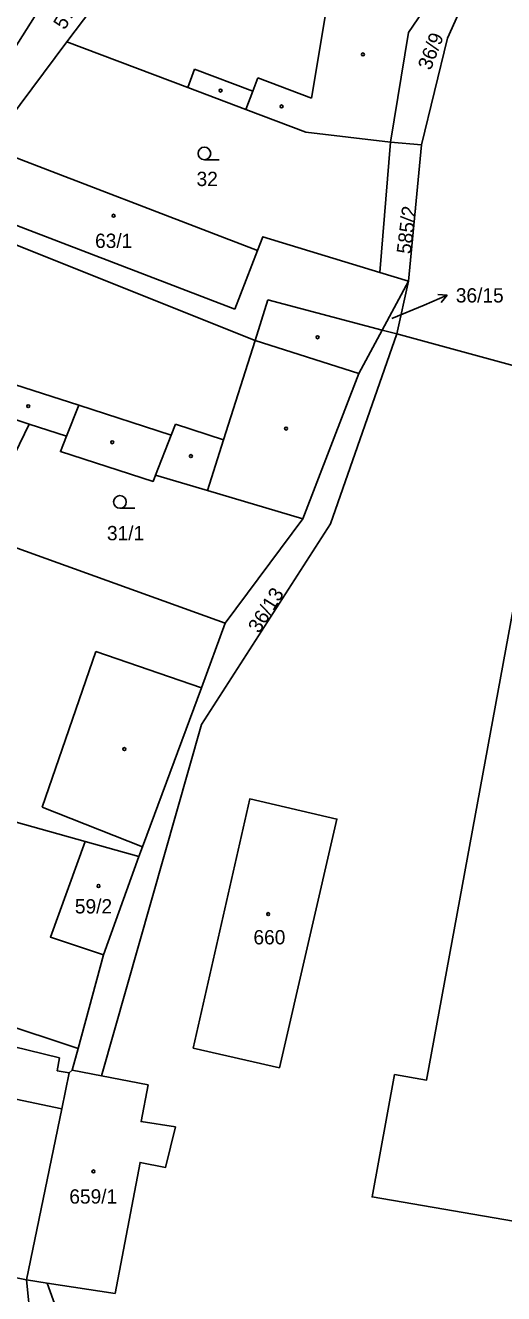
# Model space of a CAD drawing. Extents: x -783948 to -781889, y -1005870 to -1004430.
# Drawn here: x -782580.6 to -782523.7, y -1005661.9 to -1005511.3 of the extents above; entities that cross this region are included whole.
import ezdxf

# ---------------------------------------------------------------- set-up
doc = ezdxf.new("R2010")
doc.units = 0
for name, color, linetype in [('Vrstva 1', 7, 'Continuous'), ('Vrstva 2', 7, 'Continuous'), ('Vrstva 3', 7, 'Continuous'), ('Vrstva 4', 7, 'Continuous'), ('Vrstva 5', 7, 'Continuous'), ('Vrstva 7', 7, 'Continuous')]:
    doc.layers.add(name, color=color, linetype=linetype)

msp = doc.modelspace()

# ---------------------------------------------------------------- linework, layer by layer
at = {"layer": 'Vrstva 1'}
for p, q in [((-782575.65, -1005513.29), (-782585.01, -1005525.81)), ((-782538.44, -1005540.69), (-782537.19, -1005525.21)), ((-782537.19, -1005525.21), (-782533.51, -1005525.52)), ((-782533.51, -1005525.52), (-782535.06, -1005541.72)), ((-782535.06, -1005541.72), (-782538.44, -1005540.69)), ((-782538.17, -1005547.51), (-782535.06, -1005541.72)), ((-782536.45, -1005547.96), (-782535.06, -1005541.72)), ((-782540.95, -1005552.68), (-782538.17, -1005547.51)), ((-782536.45, -1005547.96), (-782538.17, -1005547.51)), ((-782547.61, -1005569.93), (-782540.95, -1005552.68)), ((-782556.83, -1005582.33), (-782547.61, -1005569.93)), ((-782556.83, -1005582.33), (-782585.34, -1005572.07)), ((-782573.46, -1005608.26), (-782584.31, -1005605.25)), ((-782567.1, -1005610.03), (-782573.46, -1005608.26)), ((-782571.28, -1005621.73), (-782567.1, -1005610.03)), ((-782574.31, -1005632.82), (-782571.28, -1005621.73)), ((-782574.31, -1005632.82), (-782587.97, -1005628.34)), ((-782575.02, -1005635.4), (-782574.31, -1005632.82)), ((-782571.53, -1005636.08), (-782575.02, -1005635.4)), ((-782565.98, -1005637.15), (-782571.53, -1005636.08)), ((-782589.64, -1005637.21), (-782576.26, -1005640.02)), ((-782580.46, -1005660.33), (-782576.26, -1005640.02)), ((-782593.5, -1005657.59), (-782580.46, -1005660.33)), ((-782580.46, -1005660.33), (-782577.99, -1005660.71)), ((-782580.46, -1005660.33), (-782579.32, -1005670.89)), ((-782577.99, -1005660.71), (-782569.93, -1005661.94))]:
    msp.add_line(p, q, dxfattribs=at)
for points in [[(-782548.22, -1005452.35), (-782556.43, -1005467.86), (-782566.82, -1005490.19), (-782588.5, -1005524.48)], [(-782562.27, -1005486.8), (-782562.84, -1005488.54), (-782571.69, -1005508), (-782575.65, -1005513.29)], [(-782533.51, -1005525.52), (-782530.41, -1005512.83), (-782526.67, -1005504.45)], [(-782537.19, -1005525.21), (-782535.04, -1005512.19), (-782532.24, -1005508.02)], [(-782575.65, -1005513.29), (-782561.29, -1005518.71), (-782554.37, -1005521.32), (-782547.24, -1005524), (-782537.19, -1005525.21)], [(-782538.44, -1005540.69), (-782552.38, -1005536.44), (-782553, -1005538.05), (-782585.01, -1005525.81)], [(-782591.08, -1005533.66), (-782553.28, -1005548.74), (-782540.95, -1005552.68)], [(-782536.45, -1005547.96), (-782544.31, -1005570.51), (-782559.66, -1005594.35), (-782571.53, -1005636.08)], [(-782452.94, -1005571.06), (-782456.68, -1005569.69), (-782536.45, -1005547.96)], [(-782580.15, -1005558.68), (-782584, -1005557.44), (-782585.78, -1005556.87), (-782591.85, -1005554.92), (-782599.07, -1005552.6)], [(-782585.34, -1005572.07), (-782582.34, -1005564.85), (-782583, -1005564.57), (-782580.15, -1005558.68)], [(-782580.15, -1005558.68), (-782575.69, -1005560.12), (-782576.41, -1005561.94), (-782565.41, -1005565.48), (-782565.11, -1005564.73), (-782558.94, -1005566.58), (-782547.61, -1005569.93)], [(-782517.64, -1005572.78), (-782521.05, -1005572.25), (-782532.9, -1005636.58), (-782536.7, -1005635.93), (-782539.38, -1005650.47), (-782518.91, -1005653.99), (-782516.23, -1005639.45), (-782520.22, -1005638.76), (-782509.61, -1005574.13), (-782510.94, -1005573.92)], [(-782567.1, -1005610.03), (-782566.67, -1005608.87), (-782559.67, -1005589.99), (-782556.83, -1005582.33)], [(-782550.4, -1005635.12), (-782560.63, -1005632.78), (-782553.91, -1005603.2), (-782543.56, -1005605.59), (-782550.4, -1005635.12)], [(-782571.28, -1005621.73), (-782577.6, -1005619.6), (-782573.46, -1005608.26)], [(-782576.26, -1005640.02), (-782575.37, -1005635.74), (-782575.02, -1005635.4)], [(-782569.93, -1005661.94), (-782566.95, -1005646.36), (-782563.92, -1005646.96), (-782562.75, -1005642.15), (-782566.84, -1005641.52), (-782565.98, -1005637.15)], [(-782577.99, -1005660.71), (-782575.15, -1005668.63), (-782553.77, -1005667.77), (-782549.87, -1005687.65), (-782550.6, -1005697.65)]]:
    msp.add_lwpolyline(points, dxfattribs=at)
at = {"layer": 'Vrstva 3'}
for p, q in [((-782559.31, -1005527.29), (-782557.56, -1005527.29)), ((-782569.34, -1005568.67), (-782567.59, -1005568.67))]:
    msp.add_line(p, q, dxfattribs=at)
for centre in [(-782559.31, -1005526.54), (-782569.34, -1005567.92)]:
    msp.add_circle(centre, 0.75, dxfattribs=at)
at = {"layer": 'Vrstva 4'}
for p, q in [((-782546.57, -1005519.96), (-782544.97, -1005510.27)), ((-782560.47, -1005516.52), (-782561.29, -1005518.71)), ((-782560.47, -1005516.52), (-782553.56, -1005519.13)), ((-782552.97, -1005517.55), (-782553.56, -1005519.13)), ((-782552.97, -1005517.55), (-782546.57, -1005519.96)), ((-782553.56, -1005519.13), (-782554.37, -1005521.32)), ((-782590.34, -1005531.77), (-782555.69, -1005545.02)), ((-782553, -1005538.05), (-782555.69, -1005545.02)), ((-782553.28, -1005548.74), (-782551.75, -1005543.93)), ((-782538.17, -1005547.51), (-782551.75, -1005543.93)), ((-782557.02, -1005560.53), (-782553.28, -1005548.74)), ((-782584.22, -1005553.24), (-782574.24, -1005556.45)), ((-782574.24, -1005556.45), (-782575.69, -1005560.12)), ((-782574.24, -1005556.45), (-782563.24, -1005559.98)), ((-782563.24, -1005559.98), (-782565.11, -1005564.73)), ((-782562.73, -1005558.69), (-782563.24, -1005559.98)), ((-782562.73, -1005558.69), (-782557.02, -1005560.53)), ((-782558.94, -1005566.58), (-782557.02, -1005560.53)), ((-782572.2, -1005585.68), (-782578.58, -1005604.18)), ((-782572.2, -1005585.68), (-782559.67, -1005589.99)), ((-782578.58, -1005604.18), (-782566.67, -1005608.87)), ((-782588.48, -1005631.05), (-782576.54, -1005633.95)), ((-782576.54, -1005633.95), (-782576.81, -1005635.47)), ((-782576.81, -1005635.47), (-782575.37, -1005635.74))]:
    msp.add_line(p, q, dxfattribs=at)
at = {"layer": 'Vrstva 5'}
for centre in [(-782540.47, -1005514.78), (-782557.39, -1005519.07), (-782550.14, -1005520.95), (-782570.1, -1005533.94), (-782545.86, -1005548.36), (-782580.24, -1005556.55), (-782549.6, -1005559.21), (-782570.26, -1005560.84), (-782560.91, -1005562.48), (-782568.82, -1005597.28), (-782571.89, -1005613.54), (-782551.73, -1005616.87), (-782572.49, -1005647.44)]:
    msp.add_circle(centre, 0.175, dxfattribs=at)
at = {"layer": 'Vrstva 7'}
for p, q in [((-782533.2, -1005544.54), (-782530.44, -1005543.37)), ((-782530.44, -1005543.37), (-782531.56, -1005543.3)), ((-782530.44, -1005543.37), (-782531.16, -1005544.22)), ((-782537.05, -1005546.14), (-782533.2, -1005544.54))]:
    msp.add_line(p, q, dxfattribs=at)

# ---------------------------------------------------------------- texts
at = {"layer": 'Vrstva 2'}
for s, rotation, p in [('577/2', 59, (-782575.91, -1005511.94)), ('36/9', 69, (-782532.42, -1005516.75)), ('585/2', 83, (-782534.79, -1005538.54)), ('36/13', 58, (-782552.8, -1005583.62))]:
    msp.add_text(s, height=1.7, rotation=rotation, dxfattribs=at).set_placement(p)
for s, p in [('32', (-782560.24, -1005530.41)), ('63/1', (-782572.3, -1005537.76)), ('36/15', (-782529.43, -1005544.24)), ('31/1', (-782570.89, -1005572.48)), ('59/2', (-782574.7, -1005616.8)), ('660', (-782553.48, -1005620.47)), ('659/1', (-782575.36, -1005651.26))]:
    msp.add_text(s, height=1.7, dxfattribs=at).set_placement(p)

doc.saveas('drawing.dxf')
